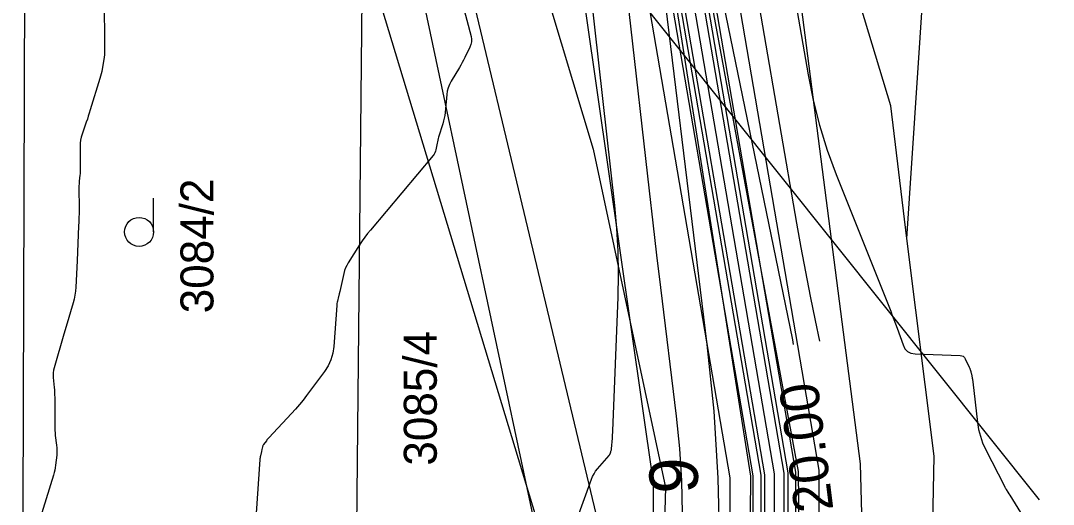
# Model space of a CAD drawing. Extents: x -534410 to -534262, y -1190162 to -1189584.
# Drawn here: x -534342.11 to -534315.47, y -1190022.24 to -1190009.76 of the extents above; entities that cross this region are included whole.
import ezdxf

# ---------------------------------------------------------------- set-up
doc = ezdxf.new("R2010")
doc.units = 0
for name, color, linetype in [('07_ELEKTRO', 7, 'Continuous'), ('30', 7, 'Continuous'), ('31', 7, 'Continuous'), ('40', 7, 'Continuous'), ('_linie', 7, 'Continuous'), ('_N_osa', 7, 'Continuous'), ('_N_tenká', 7, 'Continuous'), ('_N_tenká_velmi', 7, 'Continuous'), ('_přístup', 7, 'Continuous'), ('_tenka', 7, 'Continuous'), ('Default', 7, 'Continuous'), ('Hranice parcel', 7, 'Continuous'), ('Parcelní čísla', 7, 'Continuous'), ('Vrstva 12', 7, 'Continuous'), ('Značky kultur', 7, 'Continuous')]:
    doc.layers.add(name, color=color, linetype=linetype)

msp = doc.modelspace()

# ---------------------------------------------------------------- linework, layer by layer
at = {"layer": '07_ELEKTRO'}
msp.add_lwpolyline([(-534329.31, -1190087.46), (-534329.03, -1190079.95), (-534329.01, -1190078.66), (-534328.95, -1190069.47), (-534328.91, -1190061.75), (-534328.68, -1190054.09), (-534328.55, -1190046.44), (-534328.261, -1190025.497), (-534332.174, -1190007.081), (-534334.321, -1190004.167), (-534336.852, -1190002.737), (-534339.713, -1190001.803)], dxfattribs=at)
at = {"layer": '30'}
for points in [[(-534322.716, -1190005.85), (-534321.8, -1190011.157), (-534321.669, -1190011.814), (-534321.505, -1190012.462), (-534321.307, -1190013.1), (-534321.075, -1190013.729), (-534319.67, -1190017.258), (-534319.628, -1190017.366), (-534319.586, -1190017.474), (-534319.546, -1190017.583), (-534319.506, -1190017.692), (-534319.35, -1190018.129), (-534319.302, -1190018.225), (-534319.234, -1190018.295), (-534319.147, -1190018.338), (-534319.04, -1190018.356), (-534317.875, -1190018.4), (-534317.833, -1190018.406), (-534317.797, -1190018.422), (-534317.768, -1190018.449), (-534317.745, -1190018.484), (-534317.641, -1190018.702), (-534317.635, -1190018.716), (-534317.629, -1190018.73), (-534317.624, -1190018.744), (-534317.62, -1190018.758), (-534317.603, -1190018.816), (-534317.599, -1190018.83), (-534317.595, -1190018.845), (-534317.592, -1190018.859), (-534317.588, -1190018.874), (-534317.564, -1190018.987), (-534317.559, -1190019.011), (-534317.555, -1190019.035), (-534317.551, -1190019.058), (-534317.548, -1190019.083), (-534317.43, -1190020.126), (-534317.401, -1190020.306), (-534317.357, -1190020.481), (-534317.298, -1190020.651), (-534317.223, -1190020.817), (-534316.734, -1190021.776), (-534316.724, -1190021.795), (-534316.713, -1190021.815), (-534316.702, -1190021.834), (-534316.691, -1190021.854), (-534316.644, -1190021.93), (-534316.62, -1190021.968), (-534316.597, -1190022.006), (-534316.119, -1190022.787)], [(-534324.078, -1190023.301), (-534324.117, -1190021.569), (-534324.224, -1190019.841), (-534324.401, -1190018.116), (-534325.773, -1190006.894)], [(-534328.786, -1190025.46), (-534327.388, -1190021.594), (-534327.358, -1190021.522), (-534327.322, -1190021.453), (-534327.28, -1190021.388), (-534327.231, -1190021.326), (-534326.935, -1190020.982), (-534326.929, -1190020.975), (-534326.924, -1190020.968), (-534326.92, -1190020.96), (-534326.916, -1190020.952), (-534326.896, -1190020.912), (-534326.893, -1190020.905), (-534326.891, -1190020.897), (-534326.887, -1190020.878), (-534326.884, -1190020.867), (-534326.875, -1190020.835), (-534326.873, -1190020.829), (-534326.872, -1190020.822), (-534326.871, -1190020.815), (-534326.87, -1190020.809), (-534326.848, -1190020.537), (-534326.844, -1190020.49), (-534326.841, -1190020.442), (-534326.838, -1190020.395), (-534326.836, -1190020.347), (-534326.7, -1190016.893), (-534326.687, -1190016.302), (-534326.697, -1190015.711), (-534326.73, -1190015.122), (-534326.785, -1190014.533), (-534327.509, -1190008.078)], [(-534324.111, -1190008.706), (-534322.204, -1190017.993), (-534322.181, -1190018.116)], [(-534339.957, -1190009.113), (-534339.946, -1190010.519), (-534339.947, -1190010.581), (-534339.95, -1190010.643), (-534339.957, -1190010.704), (-534339.966, -1190010.765), (-534340.009, -1190011.01), (-534340.021, -1190011.071), (-534340.035, -1190011.132), (-534340.05, -1190011.192), (-534340.067, -1190011.251), (-534340.316, -1190012.066), (-534340.341, -1190012.145), (-534340.366, -1190012.223), (-534340.391, -1190012.301), (-534340.418, -1190012.379), (-534340.524, -1190012.689), (-534340.547, -1190012.767), (-534340.564, -1190012.847), (-534340.574, -1190012.927), (-534340.576, -1190013.009), (-534340.572, -1190013.596), (-534340.573, -1190013.635), (-534340.574, -1190013.673), (-534340.577, -1190013.711), (-534340.581, -1190013.75), (-534340.6, -1190013.902), (-534340.604, -1190013.941), (-534340.606, -1190013.979), (-534340.608, -1190014.017), (-534340.609, -1190014.056), (-534340.606, -1190014.628), (-534340.606, -1190014.736), (-534340.607, -1190014.844), (-534340.61, -1190014.953), (-534340.615, -1190015.061), (-534340.646, -1190015.726), (-534340.657, -1190015.955), (-534340.689, -1190016.634), (-534340.697, -1190016.739), (-534340.711, -1190016.842), (-534340.732, -1190016.945), (-534340.758, -1190017.046), (-534340.936, -1190017.651), (-534340.996, -1190017.853), (-534341.251, -1190018.722), (-534341.266, -1190018.783), (-534341.275, -1190018.846), (-534341.277, -1190018.908), (-534341.274, -1190018.972), (-534341.247, -1190019.226), (-534341.241, -1190019.29), (-534341.237, -1190019.354), (-534341.235, -1190019.418), (-534341.234, -1190019.482), (-534341.234, -1190020.207), (-534341.233, -1190020.271), (-534341.23, -1190020.335), (-534341.224, -1190020.399), (-534341.217, -1190020.463), (-534341.183, -1190020.717), (-534341.177, -1190020.781), (-534341.174, -1190020.845), (-534341.176, -1190020.908), (-534341.181, -1190020.972), (-534341.212, -1190021.232), (-534341.221, -1190021.296), (-534341.233, -1190021.359), (-534341.248, -1190021.422), (-534341.265, -1190021.485), (-534341.645, -1190022.709)]]:
    msp.add_lwpolyline(points, dxfattribs=at)
at = {"layer": '31'}
for points in [[(-534325.036, -1190022.469), (-534325.055, -1190021.635), (-534325.106, -1190020.801), (-534325.192, -1190019.969), (-534325.598, -1190016.645), (-534325.699, -1190015.814), (-534325.797, -1190014.982), (-534325.894, -1190014.15), (-534325.988, -1190013.318), (-534326.654, -1190007.39), (-534326.788, -1190006.444), (-534326.977, -1190005.511), (-534327.22, -1190004.59), (-534327.518, -1190003.682), (-534328.82, -1190000.077), (-534329.147, -1189999.176), (-534329.476, -1189998.275), (-534329.807, -1189997.376), (-534330.139, -1189996.477), (-534336.286, -1189979.943)], [(-534334.815, -1189980.466), (-534330.995, -1189988.966), (-534330.298, -1189990.512), (-534329.597, -1189992.056), (-534328.893, -1189993.598), (-534328.185, -1189995.139), (-534325.187, -1190001.643), (-534324.603, -1190003.024), (-534324.113, -1190004.435), (-534323.717, -1190005.875), (-534323.414, -1190007.344), (-534322.095, -1190014.986), (-534321.984, -1190015.614), (-534321.868, -1190016.242), (-534321.747, -1190016.868), (-534321.621, -1190017.494), (-534321.51, -1190018.033)], [(-534331.344, -1190006.955), (-534330.495, -1190010.169), (-534330.483, -1190010.24), (-534330.483, -1190010.31), (-534330.496, -1190010.378), (-534330.522, -1190010.445), (-534330.652, -1190010.711), (-534330.685, -1190010.778), (-534330.72, -1190010.843), (-534330.756, -1190010.907), (-534330.793, -1190010.971), (-534331.006, -1190011.325), (-534331.05, -1190011.406), (-534331.083, -1190011.491), (-534331.107, -1190011.579), (-534331.121, -1190011.671), (-534331.165, -1190012.133), (-534331.174, -1190012.206), (-534331.186, -1190012.279), (-534331.203, -1190012.35), (-534331.223, -1190012.421), (-534331.331, -1190012.765), (-534331.342, -1190012.805), (-534331.353, -1190012.845), (-534331.362, -1190012.886), (-534331.37, -1190012.927), (-534331.4, -1190013.091), (-534331.41, -1190013.131), (-534331.424, -1190013.168), (-534331.444, -1190013.204), (-534331.468, -1190013.237), (-534333.091, -1190015.166), (-534333.165, -1190015.257), (-534333.236, -1190015.35), (-534333.303, -1190015.446), (-534333.367, -1190015.544), (-534333.664, -1190016.013), (-534333.701, -1190016.077), (-534333.731, -1190016.143), (-534333.756, -1190016.212), (-534333.775, -1190016.283), (-534333.879, -1190016.748), (-534333.894, -1190016.812), (-534333.897, -1190016.828), (-534333.901, -1190016.844), (-534333.905, -1190016.86), (-534333.909, -1190016.877), (-534333.941, -1190017.003), (-534333.947, -1190017.029), (-534333.952, -1190017.056), (-534333.955, -1190017.082), (-534333.958, -1190017.11), (-534334.034, -1190018.171), (-534334.059, -1190018.345), (-534334.107, -1190018.51), (-534334.179, -1190018.666), (-534334.274, -1190018.814), (-534334.734, -1190019.429), (-534334.826, -1190019.55), (-534334.922, -1190019.667), (-534335.02, -1190019.782), (-534335.122, -1190019.894), (-534335.708, -1190020.522), (-534335.725, -1190020.541), (-534335.742, -1190020.56), (-534335.758, -1190020.58), (-534335.773, -1190020.601), (-534335.846, -1190020.699), (-534335.854, -1190020.711), (-534335.861, -1190020.725), (-534335.867, -1190020.739), (-534335.871, -1190020.754), (-534335.889, -1190020.829), (-534335.899, -1190020.875), (-534335.926, -1190020.99), (-534335.931, -1190021.014), (-534335.935, -1190021.039), (-534335.938, -1190021.064), (-534335.941, -1190021.088), (-534336.033, -1190022.471)]]:
    msp.add_lwpolyline(points, dxfattribs=at)
at = {"layer": '_linie'}
for points in [[(-534351.8, -1189951.99), (-534346.88, -1189964.25), (-534328.11, -1190005.55), (-534325.796, -1190021.686), (-534325.86, -1190050.97), (-534326.22, -1190078.56), (-534326.79, -1190120.4), (-534329.12, -1190134.93), (-534323.49, -1190133.89), (-534321.38, -1190121.46), (-534319.59, -1190053.22), (-534320.45, -1190021.195), (-534322.75, -1190003.33), (-534340.65, -1189960.04), (-534344.52, -1189948.89)], [(-534347.45, -1189950.137), (-534345.54, -1189954.54), (-534325.02, -1190005.35), (-534322.054, -1190021.393), (-534321.72, -1190051.56), (-534322.31, -1190078.15), (-534323.81, -1190120.37), (-534326.521, -1190134.45)], [(-534328.194, -1190134.759), (-534324.85, -1190120.45), (-534324.6, -1190078.17), (-534323.54, -1190051.92), (-534323.273, -1190021.516), (-534325.81, -1190005.43), (-534346.66, -1189954.59), (-534348.342, -1189950.518)]]:
    msp.add_lwpolyline(points, dxfattribs=at)
at = {"layer": '_N_osa'}
msp.add_lwpolyline([(-534327.357, -1190134.604), (-534324.33, -1190120.41), (-534323.455, -1190078.16), (-534322.63, -1190051.74), (-534322.663, -1190021.455), (-534325.415, -1190005.39), (-534346.1, -1189954.565), (-534347.892, -1189950.326)], dxfattribs=at)
at = {"layer": '_N_tenká'}
for points in [[(-534326.133, -1190134.378), (-534323.183, -1190120.543), (-534322.305, -1190078.19), (-534321.48, -1190051.757), (-534321.513, -1190021.356), (-534324.303, -1190005.072), (-534345.038, -1189954.124), (-534346.832, -1189949.878)], [(-534328.581, -1190134.83), (-534325.477, -1190120.277), (-534324.605, -1190078.13), (-534323.78, -1190051.723), (-534323.813, -1190021.553), (-534326.527, -1190005.708), (-534347.162, -1189955.006), (-534348.951, -1189950.773)]]:
    msp.add_lwpolyline(points, dxfattribs=at)
at = {"layer": '_N_tenká_velmi'}
for points in [[(-534327.091, -1190134.555), (-534324.081, -1190120.439), (-534323.205, -1190078.166), (-534322.38, -1190051.744), (-534322.413, -1190021.433), (-534325.173, -1190005.321), (-534345.869, -1189954.469), (-534347.661, -1189950.228)], [(-534326.985, -1190134.536), (-534323.981, -1190120.45), (-534323.105, -1190078.169), (-534322.28, -1190051.745), (-534322.313, -1190021.425), (-534325.076, -1190005.293), (-534345.777, -1189954.431), (-534347.569, -1189950.189)], [(-534326.772, -1190134.496), (-534323.781, -1190120.474), (-534322.905, -1190078.174), (-534322.08, -1190051.748), (-534322.113, -1190021.407), (-534324.883, -1190005.238), (-534345.592, -1189954.354), (-534347.385, -1189950.112)], [(-534327.943, -1190134.713), (-534324.879, -1190120.346), (-534324.005, -1190078.146), (-534323.18, -1190051.732), (-534323.213, -1190021.502), (-534325.947, -1190005.542), (-534346.608, -1189954.776), (-534348.398, -1189950.54)], [(-534327.73, -1190134.673), (-534324.679, -1190120.37), (-534323.805, -1190078.151), (-534322.98, -1190051.735), (-534323.013, -1190021.485), (-534325.754, -1190005.487), (-534346.423, -1189954.699), (-534348.214, -1189950.462)], [(-534327.623, -1190134.654), (-534324.579, -1190120.381), (-534323.705, -1190078.154), (-534322.88, -1190051.736), (-534322.913, -1190021.476), (-534325.657, -1190005.459), (-534346.331, -1189954.661), (-534348.122, -1189950.423)]]:
    msp.add_lwpolyline(points, dxfattribs=at)
at = {"layer": '_přístup'}
msp.add_lwpolyline([(-534330.552, -1190135.191), (-534328.648, -1190119.819), (-534326.845, -1190024.247), (-534332.805, -1189999.297), (-534354.454, -1189948.317)], dxfattribs=at)
at = {"layer": '_tenka'}
for points in [[(-534351.8, -1189951.99), (-534346.88, -1189964.25), (-534328.11, -1190005.55), (-534325.796, -1190021.686), (-534325.86, -1190050.97), (-534326.22, -1190078.56), (-534326.79, -1190120.4), (-534329.12, -1190134.93), (-534323.49, -1190133.89), (-534321.38, -1190121.46), (-534319.59, -1190053.22), (-534320.45, -1190021.195), (-534322.75, -1190003.33), (-534340.65, -1189960.04), (-534344.52, -1189948.89)], [(-534327.55, -1190134.64), (-534323.49, -1190133.89), (-534321.38, -1190121.46), (-534319.59, -1190053.22), (-534320.45, -1190021.195), (-534322.75, -1190003.33), (-534340.65, -1189960.04), (-534344.52, -1189948.89)], [(-534347.45, -1189950.137), (-534345.54, -1189954.54), (-534325.02, -1190005.35), (-534322.054, -1190021.393), (-534321.72, -1190051.56), (-534322.31, -1190078.15), (-534323.81, -1190120.37), (-534326.521, -1190134.45)], [(-534347.45, -1189950.137), (-534345.54, -1189954.54), (-534325.02, -1190005.35), (-534322.054, -1190021.393), (-534321.72, -1190051.56), (-534322.31, -1190078.15), (-534323.81, -1190120.37), (-534326.521, -1190134.45)], [(-534328.194, -1190134.759), (-534324.85, -1190120.45), (-534324.6, -1190078.17), (-534323.54, -1190051.92), (-534323.273, -1190021.516), (-534325.81, -1190005.43), (-534346.66, -1189954.59), (-534348.342, -1189950.518)], [(-534328.194, -1190134.759), (-534324.85, -1190120.45), (-534324.6, -1190078.17), (-534323.54, -1190051.92), (-534323.273, -1190021.516), (-534325.81, -1190005.43), (-534346.66, -1189954.59), (-534348.342, -1189950.518)], [(-534351.8, -1189951.99), (-534346.88, -1189964.25), (-534328.11, -1190005.55), (-534325.796, -1190021.686), (-534325.86, -1190050.97), (-534326.22, -1190078.56), (-534326.79, -1190120.4), (-534329.12, -1190134.93), (-534327.55, -1190134.64)]]:
    msp.add_lwpolyline(points, dxfattribs=at)
at = {"layer": 'Default'}
for points in [[(-534319.59, -1190053.22), (-534320.45, -1190021.195), (-534322.75, -1190003.33)], [(-534328.11, -1190005.55), (-534325.796, -1190021.686), (-534325.86, -1190050.97)]]:
    msp.add_lwpolyline(points, dxfattribs=at)
at = {"layer": 'Hranice parcel'}
for p, q in [((-534319.25, -1190015.38), (-534314.72, -1189945.99)), ((-534333.46, -1190024.63), (-534333.29, -1190007.81)), ((-534333.29, -1190007.81), (-534328.17, -1190024.72))]:
    msp.add_line(p, q, dxfattribs=at)
for points in [[(-534319.25, -1190015.38), (-534319.67, -1190011.96), (-534324.68, -1189995.39), (-534326.36, -1189991.44)], [(-534333.99, -1189993.03), (-534331.98, -1189997.67), (-534327.34, -1190013.08), (-534325.48, -1190021.81), (-534326.93, -1190073), (-534328.13, -1190128.3), (-534328.71, -1190131.86)], [(-534342.06, -1190024.47), (-534342.05, -1190022.37), (-534341.99, -1190003.45)], [(-534318.8, -1190033.53), (-534318.55, -1190021), (-534319.25, -1190015.38)]]:
    msp.add_lwpolyline(points, dxfattribs=at)
at = {"layer": 'Vrstva 12'}
msp.add_lwpolyline([(-534315.834, -1190022.126), (-534329.125, -1190005.478), (-534340.302, -1189991.272)], dxfattribs=at)
at = {"layer": 'Značky kultur'}
msp.add_line((-534338.682, -1190015.213), (-534338.682, -1190014.338), dxfattribs=at)
msp.add_circle((-534339.057, -1190015.213), 0.375, dxfattribs=at)

# ---------------------------------------------------------------- texts
at = {"layer": '40'}
msp.add_text('220.00', height=1, rotation=97.1056, dxfattribs=at).set_placement((-534321.054, -1190023.117))
at = {"layer": '_přístup'}
msp.add_text('9', height=1.25, rotation=90, dxfattribs=at).set_placement((-534324.642, -1190021.965))
at = {"layer": 'Parcelní čísla'}
for s, p in [('3084/2', (-534337.139, -1190017.313)), ('3085/4', (-534331.378, -1190021.243))]:
    msp.add_text(s, height=0.85, rotation=90, dxfattribs=at).set_placement(p)

doc.saveas('drawing.dxf')
